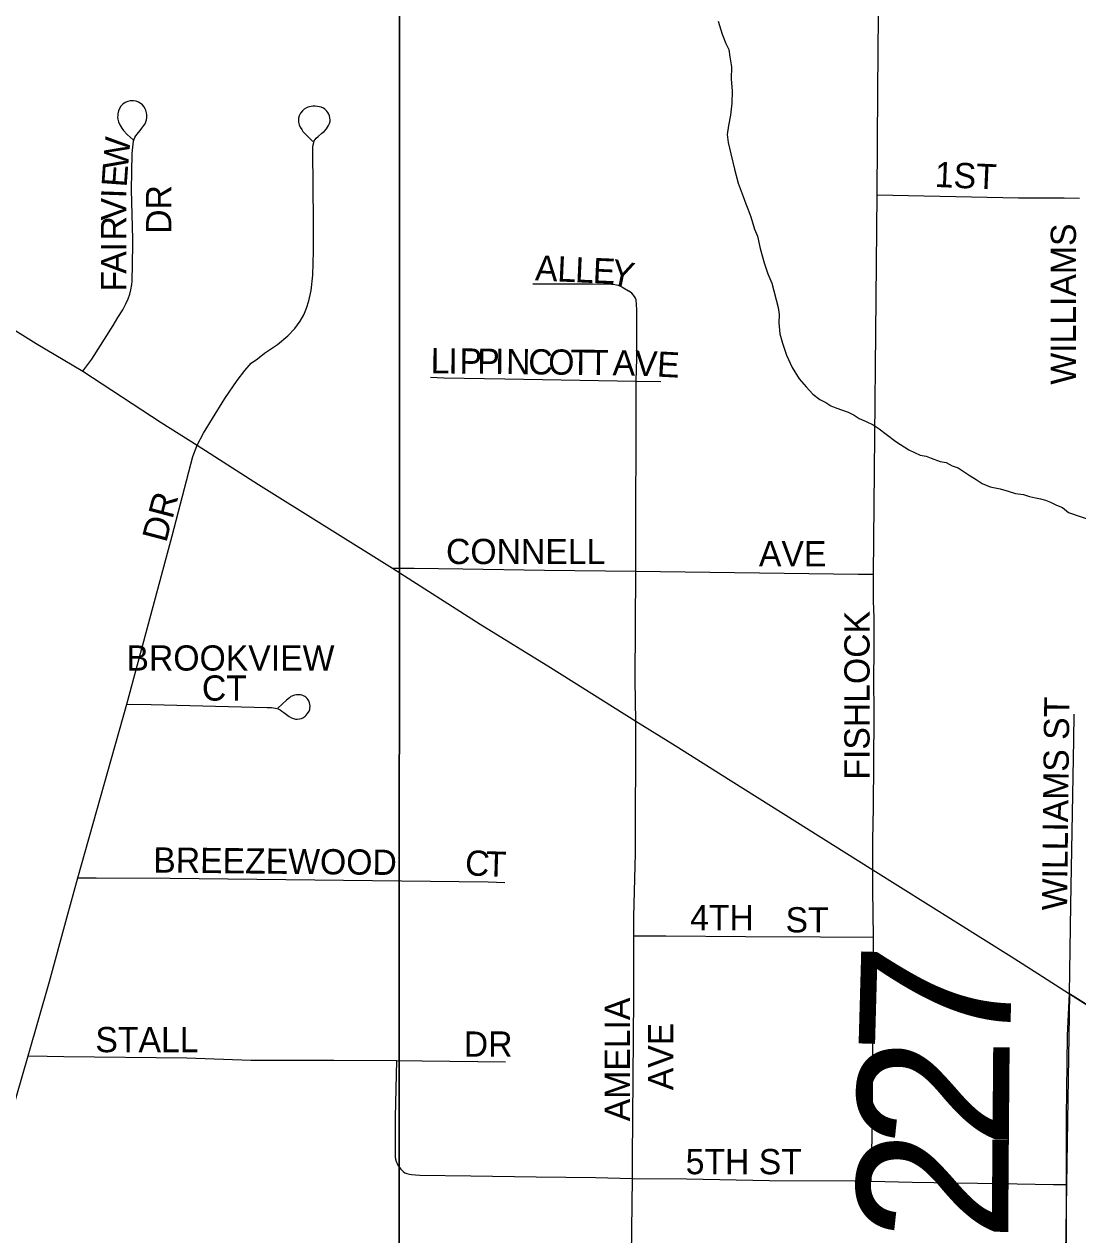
# Model space of a CAD drawing. Extents: x 1587405 to 1714697, y 1028970 to 1155083.
# Drawn here: x 1655418 to 1657507, y 1103299 to 1105700 of the extents above; entities that cross this region are included whole.
import ezdxf

# ---------------------------------------------------------------- set-up
doc = ezdxf.new("R2010")
doc.units = 0
for name, color, linetype in [('GM_X_City_Street', 7, 'Continuous'), ('GM_X_City_Street_Text', 7, 'Continuous'), ('GM_X_Corporation', 7, 'Continuous'), ('GM_X_Minor_River', 7, 'Continuous'), ('GM_X_Section', 7, 'Continuous'), ('GM_X_State_Route', 7, 'Continuous'), ('GM_X_Township_Road', 7, 'Continuous'), ('GM_X_Township_Road_Text', 7, 'Continuous')]:
    doc.layers.add(name, color=color, linetype=linetype)

msp = doc.modelspace()

# ---------------------------------------------------------------- linework, layer by layer
at = {"layer": 'GM_X_City_Street'}
for points in [[(1657109.1, 1105361.2), (1657110.5, 1105566.7), (1657112.4, 1105795.2), (1657112.2, 1105876.6), (1657113.7, 1106069.7)], [(1655534.5, 1105011.7), (1655552.1, 1105035.6), (1655594.2, 1105102.4), (1655603.5, 1105118.1), (1655613.4, 1105133.4), (1655619.7, 1105145.1), (1655624.2, 1105155.1), (1655627.4, 1105164.6), (1655629.6, 1105173.2), (1655631.1, 1105183.2), (1655631.9, 1105190), (1655632.2, 1105199.2), (1655632.9, 1105214.5), (1655633.6, 1105273.4), (1655631, 1105371.5), (1655632.4, 1105443.6), (1655633.2, 1105456.1), (1655635, 1105468), (1655636.2, 1105472), (1655637.5, 1105475), (1655639.4, 1105478.1), (1655641.8, 1105481.9), (1655647.8, 1105489.1), (1655651.3, 1105493.3), (1655655.5, 1105498.9), (1655657.6, 1105502.2), (1655659.5, 1105506.2), (1655660.7, 1105510.2), (1655661.4, 1105514.9), (1655661.3, 1105520.3), (1655660.8, 1105524.2), (1655659.5, 1105528.9), (1655658.1, 1105532.2), (1655655.5, 1105536.3), (1655652.4, 1105539.7), (1655648.1, 1105543.4), (1655644.7, 1105545.3), (1655640.3, 1105546.8), (1655634.4, 1105548), (1655628.3, 1105547.7), (1655623.2, 1105546.5), (1655618, 1105544.2), (1655613.5, 1105540.8), (1655609.7, 1105537.1), (1655606.9, 1105532.8), (1655605, 1105527.6), (1655603.7, 1105521.9), (1655603.4, 1105518.7), (1655603.3, 1105514.9), (1655603.7, 1105511.1), (1655605, 1105505.8), (1655607.5, 1105500.3), (1655611.5, 1105493.3), (1655614.7, 1105489), (1655622, 1105481.2), (1655634.1, 1105470.5)], [(1655760.7, 1104864.8), (1655773.4, 1104888.7), (1655791.5, 1104918), (1655815.7, 1104957.2), (1655840.2, 1104993.3), (1655855.3, 1105013.3), (1655868.3, 1105027.3), (1655880.8, 1105036.4), (1655894.7, 1105047.1), (1655920.4, 1105064.6), (1655940.5, 1105081.7), (1655954.8, 1105096.3), (1655965, 1105110.5), (1655972.2, 1105123.1), (1655977.8, 1105136.5), (1655982.2, 1105151), (1655986.7, 1105171.5), (1655990.1, 1105202), (1655991.7, 1105249.5), (1655991.7, 1105309.2), (1655990.1, 1105448.1), (1655990.5, 1105455.8), (1655991.1, 1105460.5), (1655992.1, 1105465.1), (1655993.2, 1105468.1), (1655995, 1105471.2), (1655996.9, 1105473.6), (1656000.7, 1105476.9), (1656008.2, 1105483.3), (1656012.6, 1105487.1), (1656017.6, 1105492.4), (1656021.6, 1105498.6), (1656023.5, 1105502.7), (1656024.4, 1105507.4), (1656024.6, 1105510.2), (1656024.2, 1105514.1), (1656023.4, 1105517.8), (1656022.2, 1105521.1), (1656020.1, 1105524.6), (1656018.2, 1105527), (1656014.1, 1105531.1), (1656011.6, 1105533), (1656006.9, 1105535.1), (1656003.6, 1105536.1), (1655999.8, 1105536.8), (1655994.9, 1105537.1), (1655990.2, 1105536.9), (1655984, 1105536.1), (1655980.7, 1105535.1), (1655977.6, 1105533.8), (1655973.3, 1105531.4), (1655969.5, 1105528), (1655965.9, 1105523.6), (1655964.3, 1105520.9), (1655963.3, 1105518.3), (1655962, 1105513.2), (1655961.6, 1105509.6), (1655962, 1105505.1), (1655963.4, 1105500), (1655965.1, 1105495.5), (1655968.3, 1105490.8), (1655970.8, 1105487.2), (1655974.5, 1105482.7), (1655990.2, 1105466.8)], [(1657101.9, 1104608.8), (1657109.1, 1105361.2)], [(1657109.1, 1105361.2), (1657389.3, 1105355.5), (1657480.1, 1105355.5), (1657510.4, 1105354.7)], [(1656426.4, 1105185), (1656544.5, 1105184.6), (1656582.6, 1105184.2), (1656589.2, 1105183.5), (1656595.5, 1105182), (1656603.3, 1105178.9), (1656615.9, 1105170.9)], [(1656631.5, 1104992), (1656632.8, 1105037.5), (1656632.7, 1105121.6), (1656632.5, 1105133.1), (1656632.3, 1105143.8), (1656631.2, 1105153), (1656630, 1105156.7), (1656628.4, 1105160), (1656622.9, 1105166), (1656615.9, 1105170.9)], [(1656223.5, 1104999.5), (1656250.1, 1104998.6), (1656371, 1104996.4), (1656631.5, 1104992)], [(1656630.5, 1104615.2), (1656631.5, 1104992)], [(1656631.5, 1104992), (1656680.1, 1104991.3)], [(1655621.7, 1104351.6), (1655669.3, 1104527.8), (1655711.3, 1104685.1), (1655752.6, 1104842.3), (1655760.7, 1104864.8)], [(1656148.2, 1104621.2), (1656191.4, 1104620.8), (1656288, 1104619.8), (1656449.7, 1104616.9), (1656630.5, 1104615.2)], [(1656630.6, 1104317.9), (1656629.3, 1104398.6), (1656630.5, 1104615.2)], [(1656630.5, 1104615.2), (1657071.8, 1104609.2), (1657101.9, 1104608.8)], [(1657103, 1104450.4), (1657103.2, 1104523.4), (1657102.3, 1104556.1), (1657101.9, 1104608.8)], [(1657100.6, 1104022.8), (1657100.6, 1104081.3), (1657101.7, 1104146.7), (1657103.2, 1104326.8), (1657102.8, 1104408.8), (1657103, 1104450.4)], [(1655621.7, 1104351.6), (1655669.8, 1104350.4), (1655900, 1104345), (1655908.5, 1104344.5), (1655916.6, 1104343.5), (1655921.8, 1104342), (1655925.3, 1104340.2), (1655928.9, 1104337.4), (1655932.5, 1104334.8), (1655938.1, 1104330.9), (1655943.7, 1104326.7), (1655948, 1104324.3), (1655951.9, 1104322.6), (1655955.9, 1104321.7), (1655959.5, 1104321.6), (1655963.7, 1104322.2), (1655967.7, 1104323.1), (1655971.8, 1104325.1), (1655974.9, 1104327.4), (1655977.1, 1104329.7), (1655979.2, 1104332.1), (1655981.6, 1104335.1), (1655983, 1104337.5), (1655984.1, 1104340.5), (1655984.6, 1104342.9), (1655984.9, 1104347.4), (1655984.6, 1104350.7), (1655983.8, 1104354.1), (1655982.3, 1104358), (1655981.2, 1104359.6), (1655979.1, 1104362.5), (1655976.1, 1104365.3), (1655974.2, 1104366.8), (1655970.8, 1104368.6), (1655968.4, 1104369.2), (1655965.7, 1104369.6), (1655961.8, 1104370), (1655957.6, 1104369.7), (1655953.7, 1104369.1), (1655950.8, 1104368), (1655946.9, 1104366.2), (1655943.9, 1104364.1), (1655938.1, 1104359.2), (1655920.6, 1104343.6)], [(1655524.6, 1104007), (1655621.7, 1104351.6)], [(1657490.3, 1103777.1), (1657493.5, 1103953.3), (1657499.3, 1104280.8), (1657500, 1104331.2)], [(1656626.8, 1103892.2), (1656626.9, 1103930.4), (1656630.3, 1104055), (1656630.6, 1104317.9)], [(1657102, 1103889.1), (1657100.8, 1103983.3), (1657100.6, 1104022.8)], [(1655425.8, 1103654.1), (1655468.5, 1103801.1), (1655502.7, 1103927.8), (1655524.6, 1104007)], [(1655524.6, 1104007), (1655560.8, 1104006.8), (1655707.4, 1104006.2), (1656337.9, 1103998.7), (1656370.8, 1103997.9)], [(1656624.4, 1103410.8), (1656624.4, 1103450.7), (1656626.8, 1103769.7), (1656626.8, 1103892.2)], [(1656626.8, 1103892.2), (1656690.3, 1103891.8), (1656848.1, 1103890.8), (1656997.1, 1103889.8), (1657102, 1103889.1)], [(1657097.2, 1103405.5), (1657097.9, 1103442.4), (1657099.3, 1103491.6), (1657102, 1103889.1)], [(1655228.4, 1102931.1), (1655230.8, 1102945.5), (1655238.5, 1102974), (1655336.1, 1103332.1), (1655370.9, 1103463.4), (1655425.8, 1103654.1)], [(1655425.8, 1103654.1), (1655463.7, 1103653.5), (1655496.3, 1103652.9), (1655740.7, 1103649.7), (1655867.5, 1103645.5), (1656032.2, 1103645.5), (1656156.4, 1103644.6)], [(1656156.4, 1103644.6), (1656153.4, 1103532.3), (1656153.8, 1103461.8), (1656153.7, 1103453.8), (1656154.4, 1103448.8), (1656155.6, 1103444.7), (1656157.3, 1103440.3), (1656159.7, 1103435.8), (1656162.6, 1103432.1), (1656165.1, 1103429), (1656167.6, 1103426.3), (1656169.5, 1103424.4), (1656172.6, 1103422.1), (1656176.5, 1103420.5), (1656181.8, 1103419.3), (1656185.8, 1103418.6), (1656193.8, 1103417.9), (1656202.4, 1103417.4), (1656303.6, 1103415.9), (1656433.1, 1103414), (1656551.1, 1103412.7), (1656624.4, 1103410.8)], [(1656156.4, 1103644.6), (1656207.1, 1103644.2), (1656372.2, 1103642)], [(1656621.7, 1102909.9), (1656620.9, 1103156.2), (1656624.4, 1103410.8)], [(1656624.4, 1103410.8), (1656731.2, 1103410.3), (1656895.5, 1103406.7), (1657064.3, 1103406.1), (1657097.2, 1103405.5)], [(1657097.2, 1103405.5), (1657178.7, 1103403.4), (1657351.1, 1103400.8), (1657458, 1103398.9), (1657484.7, 1103398.8)]]:
    msp.add_lwpolyline(points, dxfattribs=at)
at = {"layer": 'GM_X_Corporation'}
msp.add_lwpolyline([(1660013.6, 1108132.7), (1659992.5, 1104646), (1659461.1, 1104914.9), (1659349.2, 1104921.4), (1659344, 1103338.8), (1659336.3, 1102861.5), (1658982.8, 1102866.6), (1658983.7, 1102753.2), (1658842.9, 1102872.1), (1658419.8, 1103185), (1658402.9, 1103164.5), (1658418.3, 1103151.6), (1658415.7, 1103129.7), (1658127.5, 1103132.3), (1657841.9, 1103138.8), (1657848.8, 1103552), (1657490.3, 1103777.1), (1657484.7, 1103398.8), (1657477.2, 1102896.2), (1656621.6, 1102909.9), (1656154.5, 1102917.2), (1656130.9, 1101913.7), (1656133.6, 1100208.9)], dxfattribs=at)
at = {"layer": 'GM_X_Minor_River'}
for points in [[(1656794.3, 1105706), (1656801.8, 1105679.8), (1656809.4, 1105661.6), (1656815.2, 1105649.4), (1656816.9, 1105635.3), (1656820.5, 1105615.2), (1656820, 1105591.1), (1656821.6, 1105567), (1656821.1, 1105543), (1656818.6, 1105519), (1656814.2, 1105499), (1656811.8, 1105481)], [(1656811.8, 1105481), (1656813.5, 1105464.9), (1656819, 1105442.7), (1656826.5, 1105412.5), (1656833.9, 1105384.2), (1656843.4, 1105358), (1656849.1, 1105343.8), (1656852.9, 1105333.7), (1656858.6, 1105317.6), (1656866.2, 1105293.3), (1656871.9, 1105279.2), (1656877.4, 1105255), (1656884.9, 1105226.7), (1656892.5, 1105204.5), (1656900.1, 1105186.3), (1656913.2, 1105137.9), (1656914.9, 1105123.8), (1656914.6, 1105107.8), (1656916.1, 1105085.7), (1656921.8, 1105067.5), (1656929.3, 1105043.3), (1656940.9, 1105019), (1656954.5, 1104996.6), (1656968.2, 1104980.3), (1656981.9, 1104966), (1656995.8, 1104955.7), (1657007.7, 1104949.4), (1657017.6, 1104943.2), (1657027.5, 1104939), (1657051.5, 1104930.5), (1657063.4, 1104924.2), (1657073.3, 1104918), (1657087.2, 1104911.7), (1657101.1, 1104905.4), (1657113, 1104897.2), (1657126.8, 1104886.9), (1657146.6, 1104872.4), (1657172.3, 1104855.8), (1657194.2, 1104845.4), (1657206.2, 1104843.1), (1657216.2, 1104838.9), (1657234.1, 1104832.5), (1657246.1, 1104830.3), (1657258, 1104824), (1657269.9, 1104819.8), (1657279.8, 1104813.6), (1657291.7, 1104805.3), (1657305.6, 1104797), (1657317.5, 1104788.7), (1657333.4, 1104782.4), (1657353.4, 1104778), (1657369.3, 1104773.6), (1657383.3, 1104769.3), (1657399.3, 1104767), (1657411.3, 1104762.8), (1657423.2, 1104760.5), (1657433.2, 1104758.3), (1657443.2, 1104756.1), (1657453.2, 1104751.9), (1657465.1, 1104745.6), (1657477, 1104741.4), (1657488.9, 1104731.1), (1657538.7, 1104714.1)]]:
    msp.add_lwpolyline(points, dxfattribs=at)
at = {"layer": 'GM_X_Section'}
for points in [[(1651041.3, 1108325.5), (1656163.1, 1108222.1), (1656161.5, 1102928.9), (1650963.1, 1102991.2), (1650961.9, 1103051.3)], [(1656163.1, 1108222.1), (1661543.6, 1108095.1), (1661485.6, 1102806.5), (1656161.5, 1102928.9)]]:
    msp.add_lwpolyline(points, close=True, dxfattribs=at)
at = {"layer": 'GM_X_State_Route'}
for points in [[(1654276.8, 1105796), (1654483.5, 1105664.5), (1654534.1, 1105633.5), (1654578.7, 1105605), (1654841, 1105438.8), (1654955.4, 1105369.4), (1655258, 1105181.1), (1655441.7, 1105066.8), (1655534.5, 1105011.7), (1655689.8, 1104909.9), (1655760.7, 1104864.8), (1655882.9, 1104787.1), (1656148.2, 1104621.2), (1656322.4, 1104510.2), (1656461.8, 1104423.7), (1656630.6, 1104317.9), (1656708.6, 1104269.1), (1656819.6, 1104199.1), (1657100.6, 1104022.8), (1657375.1, 1103850.6), (1657427.8, 1103817)], [(1657427.8, 1103817), (1657490.3, 1103777.1), (1657527, 1103753.7), (1657638.7, 1103684.9), (1657763.5, 1103606.4), (1657848.8, 1103552), (1658081.4, 1103403.5), (1658419.7, 1103185), (1658549.6, 1103101.1), (1658617.6, 1103055.7), (1658670.3, 1103017.1), (1658734, 1102965.7), (1658842.9, 1102872.1), (1658883.1, 1102837.5), (1658983.7, 1102753.2)]]:
    msp.add_lwpolyline(points, dxfattribs=at)
at = {"layer": 'GM_X_Township_Road'}
for points in [[(1657484.7, 1103398.8), (1657484.6, 1103531.6), (1657486.7, 1103694.5), (1657490.3, 1103777.1)], [(1657484.7, 1103345.9), (1657484.7, 1103398.8)], [(1657477.2, 1102896.2), (1657482.6, 1103156.3), (1657484.7, 1103270.5), (1657484.7, 1103345.9)]]:
    msp.add_lwpolyline(points, dxfattribs=at)

# ---------------------------------------------------------------- texts
at = {"layer": 'GM_X_City_Street_Text'}
for s, rotation, p in [('W', 85.0674, (1655623.5, 1105410.5)), ('1ST', 357.5117, (1657222.8, 1105377.1)), ('E', 85.8988, (1655621, 1105375.5)), ('DR', 90, (1655709.6, 1105284.1)), ('V', 89.9703, (1655620.3, 1105310.5)), ('I', 88.0326, (1655620.3, 1105354)), ('R', 89.9514, (1655620.2, 1105270.9)), ('WILLIAMS', 90, (1657503.4, 1104984.9)), ('I', 89.985, (1655620.2, 1105248.9)), ('A', 89.9563, (1655620.2, 1105204.9)), ('A', 357.4203, (1656430.3, 1105191.7)), ('L', 357.4309, (1656474.3, 1105189.7)), ('L', 357.4309, (1656509.5, 1105188.1)), ('E', 357.4036, (1656544.6, 1105186.5)), ('Y', 348.5572, (1656577.8, 1105185.2)), ('F', 89.9727, (1655620.2, 1105169.7)), ('L', 359.3716, (1656223.7, 1105007.5)), ('I', 359.3609, (1656258.9, 1105007.1)), ('P', 359.3716, (1656280.9, 1105006.9)), ('P', 359.3679, (1656316.1, 1105006.5)), ('I', 359.3882, (1656351.3, 1105006.1)), ('N', 359.3661, (1656373.3, 1105005.9)), ('C', 359.3648, (1656417.3, 1105005.4)), ('O', 359.3735, (1656456.8, 1105005)), ('T', 359.3716, (1656500.8, 1105004.5)), ('T', 359.3543, (1656536, 1105004.1)), ('A', 359.1257, (1656584.4, 1105003.6)), ('V', 357.5513, (1656628, 1105002.9)), ('E', 357.0202, (1656671.8, 1105001)), ('DR', 75.2542, (1655699.6, 1104670.2)), ('CONNELL', 0, (1656254.4, 1104629.1)), ('AVE', 0, (1656874.8, 1104624.7)), ('FISHLOCK', 90, (1657094.2, 1104201.7)), ('BROOKVIEW', 0, (1655620.8, 1104417.9)), ('CT', 0, (1655770.4, 1104358.3)), ('WILLIAMS ST', 89.3488, (1657485.8, 1103942.2)), ('BREEZEWOOD', 359.4035, (1655673.7, 1104017.5)), ('C', 355.3815, (1656290.5, 1104013.1)), ('T', 358.3617, (1656332.9, 1104009.7)), ('4TH', 0, (1656738.4, 1103903.1)), ('ST', 0, (1656927.6, 1103898.7)), ('AMELIA', 90, (1656619, 1103524.1)), ('STALL', 0, (1655559.2, 1103661.1)), ('DR', 0, (1656289.6, 1103652.3)), ('AVE', 90, (1656705, 1103585.7)), ('5TH ST', 0, (1656729.6, 1103419.1))]:
    msp.add_text(s, height=50, rotation=rotation, dxfattribs=at).set_placement(p)
at = {"layer": 'GM_X_Township_Road_Text'}
for s, rotation, p in [('7', 88.3916, (1657371.8, 1103649.6)), ('2', 89.5103, (1657370.2, 1103467.8)), ('2', 89.5749, (1657368.9, 1103284.6))]:
    msp.add_text(s, height=300, rotation=rotation, dxfattribs=at).set_placement(p)

doc.saveas('drawing.dxf')
